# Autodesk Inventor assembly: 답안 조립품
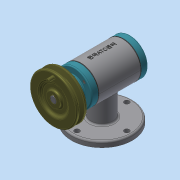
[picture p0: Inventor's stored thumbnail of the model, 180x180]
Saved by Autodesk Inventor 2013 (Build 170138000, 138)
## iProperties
Created: 2018-11
Part Number: 답안 조립품
Document SubType Name: Assembly
Designer: dgall
Author: dgall
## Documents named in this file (18)
- C:\Users\dgall\Desktop\381107V1027\답안 조립품.iam
- C:\Users\dgall\Desktop\381107V1027\본체.ipt
- C:\Users\dgall\Desktop\381107V1027\V-벨트풀리.ipt
- C:\Users\dgall\Desktop\381107V1027\가변스프링.ipt
- C:\Users\dgall\Desktop\381107V1027\뒤커버.ipt
- C:\Users\dgall\Desktop\381107V1027\멈춤나사 M3x8.ipt
- C:\Users\dgall\Desktop\381107V1027\베어링 6201.ipt
- C:\Users\dgall\Desktop\381107V1027\베어링 6202.ipt
- C:\Users\dgall\Desktop\381107V1027\본체커버.ipt
- C:\Users\dgall\Desktop\381107V1027\슬라이드.ipt
- C:\Users\dgall\Desktop\381107V1027\앞커버.ipt
- C:\Users\dgall\Desktop\381107V1027\오일 실 12 22 7.ipt
- 오일 실 12 22 7.ipt
- C:\Users\dgall\Desktop\381107V1027\키 4x4x18.ipt
- 키 4x4x18.ipt
- C:\Users\dgall\Desktop\381107V1027\편심축.ipt
- C:\Users\dgall\Desktop\381107V1027\개스킷.ipt
- C:\Users\dgall\Desktop\381107V1027\볼트 M3x0.5x8.ipt
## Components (4 placed, 3 different names)
1. V-벨트풀리:1 — 플러쉬:1
2. 가변스프링:1
3. 개스킷:1
4. 개스킷:2
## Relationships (1: Flush 1)
- 플러쉬:1 [Flush]: V-벨트풀리:1
